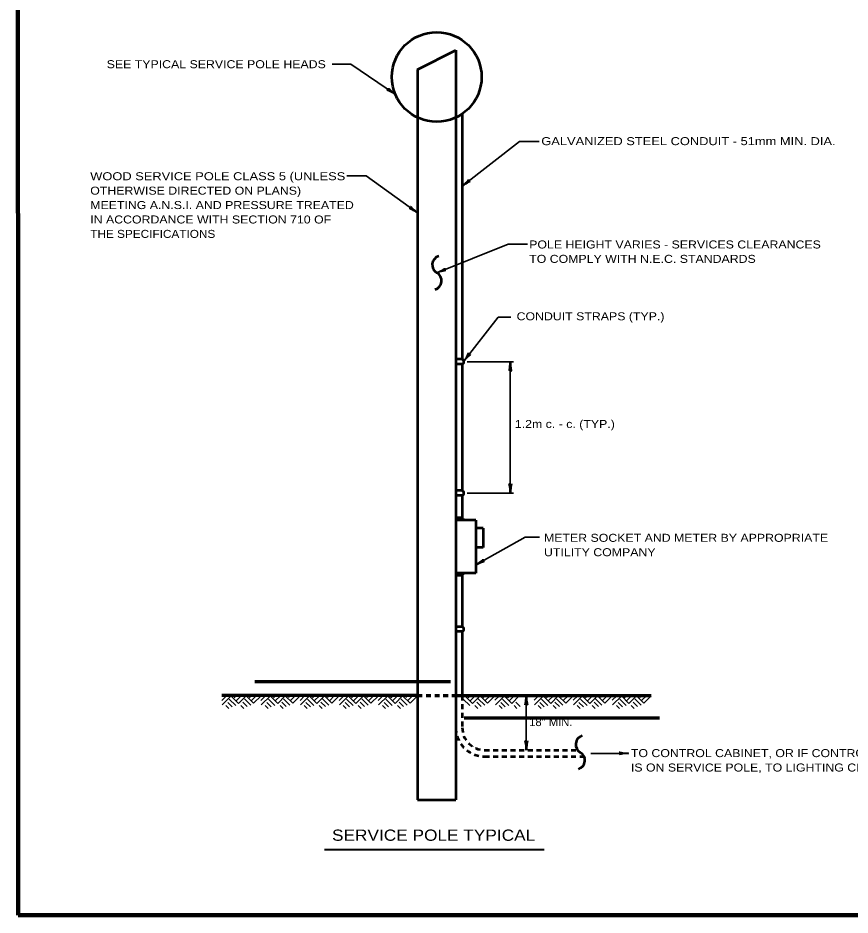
# Model space of a CAD drawing. Extents: x -33 to 680, y -7 to 447.
# Drawn here: x 15 to 274.7, y 3 to 283.1 of the extents above; entities that cross this region are included whole.
import ezdxf

# ---------------------------------------------------------------- set-up
doc = ezdxf.new("R2010")
doc.units = 0
doc.linetypes.add('SHORT_DASHED', pattern=[2.7, 1.5, -1.2])
doc.layers.add('1', color=7, linetype='Continuous', lineweight=53)

msp = doc.modelspace()

# ---------------------------------------------------------------- linework, layer by layer
at = {"layer": '1'}
for p, q in [((139.655, 267.007), (151.655, 273.007)), ((151.655, 273.007), (151.655, 39.006)), ((139.655, 267.007), (139.655, 39.006)), ((153.655, 253.006), (153.655, 176.506)), ((153.655, 176.506), (151.655, 176.506)), ((153.655, 175.006), (151.655, 175.006)), ((153.655, 175.006), (153.655, 135.506)), ((153.655, 135.506), (151.655, 135.506)), ((153.655, 134.006), (151.655, 134.006)), ((153.655, 134.006), (153.655, 126.757)), ((153.655, 127.007), (151.655, 127.007)), ((153.905, 126.757), (151.655, 126.757)), ((157.905, 126.257), (151.655, 126.257)), ((153.905, 126.757), (153.905, 126.257)), ((157.905, 126.257), (157.905, 109.757)), ((160.155, 123.757), (157.905, 123.757)), ((160.155, 123.757), (160.155, 117.757)), ((160.155, 117.757), (157.905, 117.757)), ((157.905, 109.757), (151.655, 109.757)), ((153.905, 109.257), (151.655, 109.257)), ((153.655, 109.257), (153.655, 93.007)), ((153.905, 109.257), (153.905, 109.757)), ((153.655, 109.007), (151.655, 109.007)), ((153.655, 93.007), (151.655, 93.007)), ((153.655, 91.507), (151.655, 91.507)), ((153.655, 91.507), (153.655, 71.507)), ((139.655, 39.006), (151.655, 39.006))]:
    msp.add_line(p, q, dxfattribs=at)
at = {"layer": '1', "lineweight": 35}
for p, q in [((155.166, 175.756), (169.655, 175.756)), ((168.655, 175.756), (168.655, 134.756)), ((155.166, 134.756), (169.655, 134.756)), ((80.063, 71.463), (78.633, 70.033)), ((81.602, 71.463), (78.763, 68.624)), ((80.974, 70.423), (82.989, 68.429)), ((81.494, 71.463), (83.877, 69.079)), ((83.141, 71.463), (82.534, 70.835)), ((84.701, 71.463), (83.206, 69.968)), ((86.239, 71.463), (83.877, 69.079)), ((85.676, 70.488), (87.67, 68.494)), ((86.239, 71.463), (88.558, 69.144)), ((87.778, 71.463), (87.215, 70.9)), ((89.338, 71.463), (87.908, 70.033)), ((90.877, 71.463), (88.558, 69.144)), ((92.263, 71.463), (90.833, 70.033)), ((93.802, 71.463), (90.963, 68.624)), ((93.174, 70.423), (95.189, 68.429)), ((93.694, 71.463), (96.077, 69.079)), ((95.341, 71.463), (94.734, 70.835)), ((96.901, 71.463), (95.406, 69.968)), ((98.439, 71.463), (96.077, 69.079)), ((97.876, 70.488), (99.87, 68.494)), ((98.439, 71.463), (100.758, 69.144)), ((99.978, 71.463), (99.414, 70.9)), ((101.538, 71.463), (100.108, 70.033)), ((103.077, 71.463), (100.758, 69.144)), ((104.463, 71.463), (103.033, 70.033)), ((106.002, 71.463), (103.163, 68.624)), ((105.374, 70.423), (107.389, 68.429)), ((105.894, 71.463), (108.277, 69.079)), ((107.541, 71.463), (106.934, 70.835)), ((109.101, 71.463), (107.606, 69.968)), ((110.639, 71.463), (108.277, 69.079)), ((110.076, 70.488), (112.07, 68.494)), ((110.639, 71.463), (112.958, 69.144)), ((112.178, 71.463), (111.614, 70.9)), ((113.738, 71.463), (112.308, 70.033)), ((115.277, 71.463), (112.958, 69.144)), ((116.663, 71.463), (115.233, 70.033)), ((118.202, 71.463), (115.363, 68.624)), ((117.574, 70.423), (119.589, 68.429)), ((118.094, 71.463), (120.477, 69.079)), ((119.741, 71.463), (119.134, 70.835)), ((121.301, 71.463), (119.806, 69.968)), ((122.839, 71.463), (120.477, 69.079)), ((122.276, 70.488), (124.27, 68.494)), ((122.839, 71.463), (125.158, 69.144)), ((124.378, 71.463), (123.814, 70.9)), ((125.938, 71.463), (124.508, 70.033)), ((127.477, 71.463), (125.158, 69.144)), ((128.863, 71.463), (127.433, 70.033)), ((130.402, 71.463), (127.563, 68.624)), ((129.774, 70.423), (131.789, 68.429)), ((130.294, 71.463), (132.677, 69.079)), ((131.941, 71.463), (131.334, 70.835)), ((133.501, 71.463), (132.006, 69.968)), ((135.039, 71.463), (132.677, 69.079)), ((134.476, 70.488), (136.47, 68.494)), ((135.039, 71.463), (137.358, 69.144)), ((136.578, 71.463), (136.014, 70.9)), ((138.138, 71.463), (136.708, 70.033)), ((139.677, 71.463), (137.358, 69.144)), ((153.987, 70.427), (155.995, 68.44)), ((154.505, 71.463), (156.88, 69.088)), ((156.146, 71.463), (155.542, 70.837)), ((157.701, 71.463), (156.211, 69.973)), ((159.234, 71.463), (156.88, 69.088)), ((158.673, 70.492), (160.659, 68.505)), ((159.234, 71.463), (161.545, 69.153)), ((160.767, 71.463), (160.206, 70.902)), ((162.322, 71.463), (160.897, 70.038)), ((163.855, 71.463), (161.545, 69.153)), ((165.28, 71.463), (163.855, 70.038)), ((166.813, 71.463), (163.985, 68.635)), ((166.187, 70.427), (168.195, 68.44)), ((166.705, 71.463), (169.081, 69.088)), ((168.346, 71.463), (167.742, 70.837)), ((169.901, 71.463), (168.411, 69.973)), ((171.434, 71.463), (169.081, 69.088)), ((173.655, 71.507), (173.655, 54.506)), ((177.48, 71.463), (176.055, 70.038)), ((179.013, 71.463), (176.185, 68.635)), ((178.387, 70.427), (180.395, 68.44)), ((178.905, 71.463), (181.28, 69.088)), ((180.546, 71.463), (179.942, 70.837)), ((182.101, 71.463), (180.611, 69.973)), ((183.634, 71.463), (181.28, 69.088)), ((183.073, 70.492), (185.059, 68.505)), ((183.634, 71.463), (185.945, 69.153)), ((185.167, 71.463), (184.606, 70.902)), ((186.722, 71.463), (185.297, 70.038)), ((188.255, 71.463), (185.945, 69.153)), ((189.68, 71.463), (188.255, 70.038)), ((191.213, 71.463), (188.385, 68.635)), ((190.587, 70.427), (192.595, 68.44)), ((191.105, 71.463), (193.481, 69.088)), ((192.746, 71.463), (192.142, 70.837)), ((194.301, 71.463), (192.811, 69.973)), ((195.834, 71.463), (193.481, 69.088)), ((195.273, 70.492), (197.259, 68.505)), ((195.834, 71.463), (198.145, 69.153)), ((197.367, 71.463), (196.806, 70.902)), ((198.922, 71.463), (197.497, 70.038)), ((200.455, 71.463), (198.145, 69.153)), ((201.88, 71.463), (200.455, 70.038)), ((203.413, 71.463), (200.585, 68.635)), ((202.787, 70.427), (204.795, 68.44)), ((203.305, 71.463), (205.68, 69.088)), ((204.946, 71.463), (204.342, 70.837)), ((206.501, 71.463), (205.011, 69.973)), ((208.034, 71.463), (205.68, 69.088)), ((207.473, 70.492), (209.459, 68.505)), ((208.034, 71.463), (210.345, 69.153)), ((209.567, 71.463), (209.006, 70.902)), ((211.122, 71.463), (209.697, 70.038)), ((212.655, 71.463), (210.345, 69.153)), ((79.933, 68.386), (80.865, 67.476)), ((80.475, 69.383), (81.862, 67.996)), ((84.614, 68.451), (85.546, 67.519)), ((85.178, 69.448), (86.564, 68.061)), ((92.133, 68.386), (93.065, 67.476)), ((92.675, 69.383), (94.062, 67.996)), ((96.814, 68.451), (97.746, 67.519)), ((97.378, 69.448), (98.764, 68.061)), ((104.334, 68.386), (105.265, 67.476)), ((104.875, 69.383), (106.262, 67.996)), ((109.014, 68.451), (109.946, 67.519)), ((109.578, 69.448), (110.964, 68.061)), ((116.533, 68.386), (117.465, 67.476)), ((117.075, 69.383), (118.462, 67.996)), ((121.214, 68.451), (122.146, 67.519)), ((121.778, 69.448), (123.164, 68.061)), ((128.733, 68.386), (129.665, 67.476)), ((129.275, 69.383), (130.662, 67.996)), ((133.414, 68.451), (134.346, 67.519)), ((133.978, 69.448), (135.364, 68.061)), ((157.615, 68.462), (158.543, 67.533)), ((158.176, 69.455), (159.558, 68.073)), ((165.151, 68.397), (166.079, 67.49)), ((165.69, 69.39), (167.072, 68.008)), ((169.815, 68.462), (170.743, 67.533)), ((170.376, 69.455), (171.758, 68.073)), ((177.351, 68.397), (178.279, 67.49)), ((177.89, 69.39), (179.272, 68.008)), ((182.015, 68.462), (182.943, 67.533)), ((182.576, 69.455), (183.958, 68.073)), ((189.551, 68.397), (190.479, 67.49)), ((190.09, 69.39), (191.472, 68.008)), ((194.215, 68.462), (195.143, 67.533)), ((194.776, 69.455), (196.158, 68.073)), ((201.751, 68.397), (202.679, 67.49)), ((202.29, 69.39), (203.672, 68.008)), ((206.415, 68.462), (207.343, 67.533)), ((206.976, 69.455), (208.358, 68.073)), ((193.744, 53.469), (205.504, 53.469))]:
    msp.add_line(p, q, dxfattribs=at)
at = {"layer": '1', "lineweight": 70}
for p, q in [((149.976, 75.758), (88.976, 75.758)), ((139.655, 71.507), (78.655, 71.507)), ((151.655, 71.507), (212.655, 71.507)), ((154.251, 64.596), (215.251, 64.596))]:
    msp.add_line(p, q, dxfattribs=at)
at = {"layer": '1', "linetype": 'SHORT_DASHED', "lineweight": 70}
msp.add_line((139.655, 71.507), (151.655, 71.507), dxfattribs=at)
at = {"layer": '1', "linetype": 'SHORT_DASHED'}
for p, q in [((153.655, 71.507), (153.655, 61.506)), ((160.655, 54.506), (189.675, 54.506)), ((160.655, 52.506), (191.682, 52.506))]:
    msp.add_line(p, q, dxfattribs=at)
at = {"layer": '1', "lineweight": 40}
msp.add_line((110.694, 23.47), (179.194, 23.47), dxfattribs=at)
at = {"layer": '1', "lineweight": 158}
msp.add_line((674.767, 2.994), (15.1, 2.994), dxfattribs=at)
msp.add_lwpolyline([(674.767, 441.411), (15.017, 441.328), (15.1, 2.994)], dxfattribs=at)
at = {"layer": '1', "lineweight": 35}
for points in [[(132.783, 259.219), (118.854, 268.685), (113.033, 268.685)], [(153.655, 230.572), (171.492, 244.466), (177.637, 244.466)], [(139.655, 222.258), (123.705, 233.746), (117.668, 233.746)], [(145.754, 203.505), (167.996, 212.412), (174.012, 212.412)], [(154.14, 175.961), (164.902, 189.671), (168.819, 189.671)], [(157.905, 112.289), (173.287, 120.944), (177.756, 120.944)]]:
    msp.add_lwpolyline(points, dxfattribs=at)
at = {"layer": '1'}
msp.add_circle((145.689, 264.645), 14, dxfattribs=at)
for centre, radius, start, end in [((147.182, 205.999), 2.874, 107.80152, 240.19848), ((144.326, 201.011), 2.874, 287.80152, 60.19848), ((153.36, 175.756), 0.806, 291.45652, 68.54348), ((153.36, 134.756), 0.806, 291.45652, 68.54348), ((153.36, 92.257), 0.806, 291.45652, 68.54348), ((191.93, 56.288), 2.874, 107.80152, 240.19848), ((189.073, 51.3), 2.874, 287.80152, 60.19848)]:
    msp.add_arc(centre, radius, start, end, dxfattribs=at)
at = {"layer": '1', "linetype": 'SHORT_DASHED'}
for radius in [9, 7]:
    msp.add_arc((160.655, 61.506), radius, 180, 270, dxfattribs=at)
at = {"layer": '1', "lineweight": 40}
for centre, major_axis, ratio, start_param, end_param in [((131.725, 259.604), (1.565, -0.875), 0.122415, 0.8963533, 3.1415927), ((131.975, 260.024), (-1.354, 1.133), 0.07063, 6.2823074, 8.5597026), ((154.346, 231.46), (-1.313, -1.221), 0.122415, 0.8963533, 3.1415927), ((154.346, 231.46), (-1.313, -1.221), 0.122415, 0.8963533, 3.1415927), ((154.669, 231.094), (1.494, 0.941), 0.07063, 6.2823074, 8.5597026), ((154.669, 231.094), (1.494, 0.941), 0.07063, 6.2823074, 8.5597026), ((138.869, 223.085), (-1.323, 1.169), 0.07063, 6.2823074, 8.5597026), ((138.869, 223.085), (-1.323, 1.169), 0.07063, 6.2823074, 8.5597026), ((138.608, 222.672), (1.54, -0.917), 0.122415, 0.8963533, 3.1415927), ((138.608, 222.672), (1.54, -0.917), 0.122415, 0.8963533, 3.1415927), ((146.664, 204.167), (-1.6, -0.809), 0.122415, 0.8963533, 3.1415927), ((146.664, 204.167), (-1.6, -0.809), 0.122415, 0.8963533, 3.1415927), ((146.873, 203.725), (1.696, 0.49), 0.07063, 6.2823074, 8.5597026), ((146.873, 203.725), (1.696, 0.49), 0.07063, 6.2823074, 8.5597026), ((154.596, 176.99), (-0.98, -1.501), 0.122415, 0.8963533, 3.1415927), ((154.998, 176.712), (1.223, 1.273), 0.07063, 6.2823074, 8.5597026), ((168.443, 174.636), (0.176, 1.756), 0.07063, 3.1407148, 5.41811), ((168.443, 174.636), (0.176, 1.756), 0.07063, 3.1407148, 5.41811), ((168.931, 174.665), (-0.156, 1.786), 0.122415, 0.8963533, 3.1415927), ((168.931, 174.665), (-0.156, 1.786), 0.122415, 0.8963533, 3.1415927), ((168.379, 135.848), (0.156, -1.786), 0.122415, 0.8963533, 3.1415927), ((168.379, 135.848), (0.156, -1.786), 0.122415, 0.8963533, 3.1415927), ((168.867, 135.877), (-0.176, -1.756), 0.07063, 3.1407148, 5.41811), ((168.867, 135.877), (-0.176, -1.756), 0.07063, 3.1407148, 5.41811), ((158.72, 113.065), (-1.48, -1.012), 0.122415, 0.8963533, 3.1415927), ((158.72, 113.065), (-1.48, -1.012), 0.122415, 0.8963533, 3.1415927), ((158.985, 112.654), (1.617, 0.708), 0.07063, 6.2823074, 8.5597026), ((158.985, 112.654), (1.617, 0.708), 0.07063, 6.2823074, 8.5597026), ((173.443, 70.386), (0.176, 1.756), 0.07063, 3.1407148, 5.41811), ((173.931, 70.415), (-0.156, 1.786), 0.122415, 0.8963533, 3.1415927), ((173.379, 55.598), (0.156, -1.786), 0.122415, 0.8963533, 3.1415927), ((173.867, 55.627), (-0.176, -1.756), 0.07063, 3.1407148, 5.41811), ((204.412, 53.193), (1.786, 0.156), 0.122415, 0.8963533, 3.1415927), ((204.383, 53.681), (1.756, -0.176), 0.07063, 3.1407148, 5.41811)]:
    msp.add_ellipse(centre, major_axis=major_axis, ratio=ratio, start_param=start_param, end_param=end_param, dxfattribs=at)

# ---------------------------------------------------------------- texts
at = {"layer": '1'}
for s, height, width, p in [('SEE TYPICAL SERVICE POLE HEADS', 2.5, 1.15, (42.71, 267.388)), ('GALVANIZED STEEL CONDUIT - 51mm MIN. DIA.', 2.5, 1.2, (178.322, 243.369)), ('WOOD SERVICE POLE CLASS 5 (UNLESS', 2.5, 1.2, (37.575, 232.41)), ('OTHERWISE DIRECTED ON PLANS)', 2.5, 1.15, (37.575, 227.91)), ('MEETING A.N.S.I. AND PRESSURE TREATED', 2.5, 1.15, (37.575, 223.41)), ('IN ACCORDANCE WITH SECTION 710 OF', 2.5, 1.15, (37.575, 218.91)), ('THE SPECIFICATIONS', 2.5, 1.1, (37.575, 214.41)), ('POLE HEIGHT VARIES - SERVICES CLEARANCES', 2.5, 1.15, (174.546, 211.11)), ('TO COMPLY WITH N.E.C. STANDARDS', 2.5, 1.15, (174.546, 206.61)), ('CONDUIT STRAPS (TYP.)', 2.5, 1.15, (170.62, 188.684)), ('1.2m c. - c. (TYP.)', 2.5, 1.15, (170.084, 155.053)), ('METER SOCKET AND METER BY APPROPRIATE', 2.5, 1.15, (179.17, 119.523)), ('UTILITY COMPANY', 2.5, 1.15, (179.17, 115.023)), ('18" MIN.', 2.5, 1.05, (174.533, 61.996)), ('TO CONTROL CABINET, OR IF CONTROL CABINET', 2.5, 1.15, (206.29, 52.306)), ('IS ON SERVICE POLE, TO LIGHTING CIRCUITS', 2.5, 1.15, (206.29, 47.806)), ('SERVICE POLE TYPICAL', 3.5, 1.15, (113.021, 26.185))]:
    msp.add_text(s, height=height, dxfattribs=dict(at, width=width)).set_placement(p)

doc.saveas('drawing.dxf')
